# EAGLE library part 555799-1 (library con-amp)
AMP connector
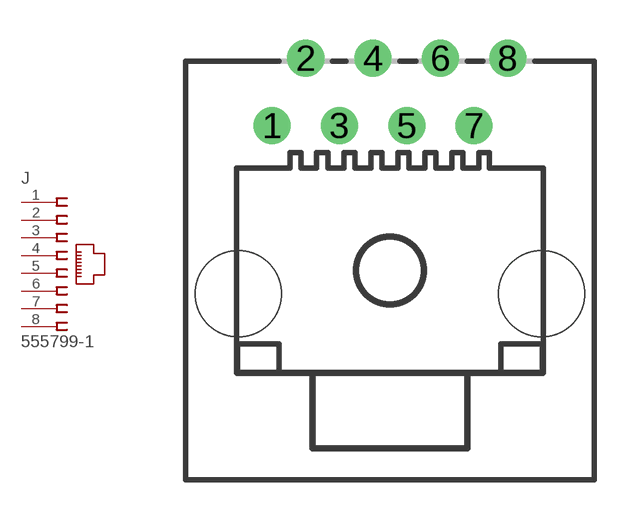
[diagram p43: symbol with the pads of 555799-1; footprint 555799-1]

Designator prefix J

## 555799-1 (MF: TYCO ELECTRONICS; MPN: 5555799-1; OC_FARNELL: 1557722; OC_NEWARK: 42K8767)  [555799-1]
1  1  pas
2  2  pas
3  3  pas
4  4  pas
5  5  pas
6  6  pas
7  7  pas
8  8  pas

## Footprint 555799-1 (pad centres in mm)
Modular Jack without Panel Stops
drill 0.889 round: 1 -4.445,5.461; 2 -3.175,8.001; 3 -1.905,5.461; 4 -0.635,8.001; 5 0.635,5.461; 6 1.905,8.001; 7 3.175,5.461; 8 4.445,8.001
hole 3.251 at -5.715,-0.889
hole 3.251 at 5.715,-0.889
